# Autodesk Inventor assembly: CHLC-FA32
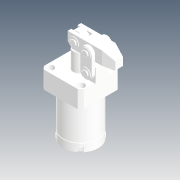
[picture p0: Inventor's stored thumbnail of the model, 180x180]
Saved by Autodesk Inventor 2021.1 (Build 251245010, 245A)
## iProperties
Company: Microsoft
Created: 2019-11
Part Number: CHLC-FA32
Description: STEP AP214
Document SubType Name: Assembly
Designer: user
Title: CHLC-FA32.STEP
Author: Windows
Revision Number: ÈÎºÎ
Sending System: SolidWorks 2015
Preprocessor: SwSTEP 2.0
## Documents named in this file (10)
- D:\Vault_2016\Projekty\Clamptek\Hydraulic\CHLC\CHLC-32\Inventor\CHLC-FA32\CHLC-FA32.iam
- D:\Vault_2016\Projekty\Clamptek\Hydraulic\CHLC\CHLC-32\Inventor\CHLC-FA32\CHLC-FA32-05.ipt
- D:\Vault_2016\Projekty\Clamptek\Hydraulic\CHLC\CHLC-32\Inventor\CHLC-FA32\CHLC-FA32-10.ipt
- D:\Vault_2016\Projekty\Clamptek\Hydraulic\CHLC\CHLC-32\Inventor\CHLC-FA32\CHLC-32-08_1.ipt
- D:\Vault_2016\Projekty\Clamptek\Hydraulic\CHLC\CHLC-32\Inventor\CHLC-FA32\CHLC-32-03.ipt
- D:\Vault_2016\Projekty\Clamptek\Hydraulic\CHLC\CHLC-32\Inventor\CHLC-FA32\CHLC-32-02.ipt
- D:\Vault_2016\Projekty\Clamptek\Hydraulic\CHLC\CHLC-32\Inventor\CHLC-FA32\CHLC-32-04.ipt
- D:\Vault_2016\Projekty\Clamptek\Hydraulic\CHLC\CHLC-32\Inventor\CHLC-FA32\LHC01D-40-08.ipt
- D:\Vault_2016\Projekty\Clamptek\Hydraulic\CHLC\CHLC-32\Inventor\CHLC-FA32\M6LC.ipt
- D:\Vault_2016\Projekty\Clamptek\Hydraulic\CHLC\CHLC-32\Inventor\CHLC-FA32\Ñ¹±Û.ipt
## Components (19 placed, 19 different names)
1. CHLC-FA32-05_1
2. CHLC-FA32-10_2
3. CHLC-32-08_1_3
4. CHLC-32-03_4
5. CHLC-32-03_5
6. CHLC-32-02_6
7. CHLC-32-04_7
8. CHLC-32-04_8
9. LHC01D-40-08_9
10. LHC01D-40-08_10
11. LHC01D-40-08_11
12. LHC01D-40-08_12
13. LHC01D-40-08_13
14. LHC01D-40-08_14
15. M6LC_15
16. M6LC_16
17. M6LC_17
18. M6LC_18
19. Ñ¹±Û_19
